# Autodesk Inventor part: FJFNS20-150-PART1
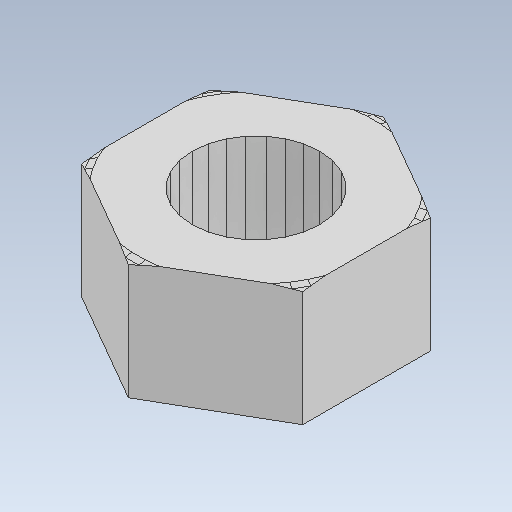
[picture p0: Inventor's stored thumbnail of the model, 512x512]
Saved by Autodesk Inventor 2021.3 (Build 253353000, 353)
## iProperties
Created: 2022-02
Part Number: FJFNS20-150-PART1
Material: 一般
Document SubType Name: Modeling
Designer: kengo
Density: 1 g/cm^3
Appearance: 既定
Author: kengo
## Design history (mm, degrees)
feature "FJFNS20-150-PART1"
node "ソリッド1"
